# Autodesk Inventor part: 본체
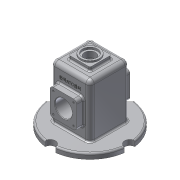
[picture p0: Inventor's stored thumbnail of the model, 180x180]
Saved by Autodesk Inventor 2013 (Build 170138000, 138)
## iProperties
Created: 2018-07
Part Number: 본체
Material: 알루미늄 6061
Document SubType Name: Modeling
Designer: dgall
Density: 1 g/cm^3
Author: dgall
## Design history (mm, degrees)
sketch "스케치1"
  geometry: L1 (-37, -37)-(37, -37); L2 (37, -37)-(37, 37); L3 (37, 37)-(-37, 37); L4 (-37, 37)-(-37, -37); L5 (-37, -37)-(37, 37); L6 (37, -37)-(-37, 37); 1 further point
  constraints: 12 end point, 2 midpoint, 2 parallel, 1 horizontal, 1 perpendicular
  dimensions: "d0" = 74 distance of L3.end L1.start; "d1" = 74 distance of L2.end L3.end
extrude "돌출1" new body sketch "스케치1" distance "d2" = 110; taper "d3" = 0 deg
sketch "스케치2"
  geometry: C1 r 75 at (0, 0); 1 further point
  constraints: 1 centre point, 1 coincident
  dimensions: "d4" = 150 diameter of C1
extrude "돌출2" join sketch "스케치2" distance "d6" = 10; taper "d7" = 0 deg
sketch "스케치3"
  geometry: L1 (-20, -20)-(20, -20); L2 (20, -20)-(20, 20); L3 (20, 20)-(-20, 20); L4 (-20, 20)-(-20, -20); L5 (-20, -20)-(20, 20); L6 (20, -20)-(-20, 20); 1 further point
  constraints: 12 end point, 2 midpoint, 2 parallel, 1 horizontal, 1 perpendicular
  dimensions: "d8" = 40 distance of L2.end L3.end; "d9" = 40 distance of L1.end L2.end
extrude "돌출3" join sketch "스케치3" distance "d10" = 7; taper "d11" = 0 deg
sketch "스케치4"
  geometry: C1 r 75 at (0, 0) reference; C2 r 17.5 at (0, 0); 1 further point
  constraints: 1 centre point, 1 coincident
  dimensions: "d12" = 35 diameter of C2
extrude "돌출4" join sketch "스케치4" distance "d14" = 3; taper "d15" = 0 deg
sketch "스케치5"
  geometry: L1 (-25, 30)-(25, 30); L2 (25, 30)-(25, 80); L3 (25, 80)-(-25, 80); L4 (-25, 80)-(-25, 30); L5 (-25, 30)-(25, 80); L6 (25, 30)-(-25, 80); L7 (-75, 0)-(75, 0) reference; L8 (-37, 10)-(-37, 110) reference; 3 further points
  constraints: 12 end point, 2 midpoint, 2 parallel, 1 horizontal, 1 perpendicular
  dimensions: "d17" = 50 distance of L2.end L3.end; "d19" = 50 distance of L3.end L1.start; "d20" = 55 distance from line of L7 point (0, 55); "d21" = 37 distance from line of L8 point (0, 55)
extrude "돌출5" join sketch "스케치5" stored distance "d22" = 100; taper "d23" = 0 deg
fillet "모깎기2" dims "d24" = 6
fillet "모깎기3" dims "d25" = 3
sketch "스케치6"
  geometry: C1 r 17.5 at (0, 0) reference
hole "구멍1" sketch "스케치6" at (0, 0) diameter "d27" = 21; stored, may be unused: countersink angle "d31" = 90 deg, drill point angle "d33" = 118 deg; dims "d28" = 6, "d29" = 28, "d30" = 4, "d32" = 21
sketch "스케치7"
  geometry: L1 (0, -75)-(0, 75) reference; C1 r 16 at (-55, 0); 2 further points
  constraints: 1 centre point, 1 horizontal alignment, 1 midpoint
  dimensions: "d34" = 32 diameter of C1; "d36" = 55 distance from line of L1 C1.centre
extrude "돌출6" cut sketch "스케치7" stored distance "d37" = 100; taper "d38" = 0 deg
sketch "스케치8"
  geometry: L1 (-32, 0)-(32, 0); L2 (32, 0)-(32, 105); L3 (32, 105)-(-32, 105); L4 (-32, 105)-(-32, 0); L5 (-32, 0)-(32, 105); L6 (32, 0)-(-32, 105); L7 (-29, 110)-(29, 110) reference; 3 further points
  constraints: 12 end point, 3 midpoint, 2 parallel, 1 coincident, 1 horizontal, 1 perpendicular
  dimensions: "d39" = 64 distance of L2.end L3.end; "d41" = 5 distance between parallel lines of L3 L7
extrude "돌출7" cut sketch "스케치8" stored distance "d42" = 64; taper "d43" = 0 deg
sketch "스케치9"
  geometry: L1 (32, 80)-(25, 77.452); L2 (25, 77.452)-(25, 55); L3 (40, 74)-(40, 36) reference; L4 (25, 55)-(32, 55); L5 (32, 55)-(32, 80); L6 (32, 71)-(32, 39) reference; L7 (32, 0)-(-32, 0) reference; L8 (32, 0)-(32, 105) reference; 1 further point
  constraints: 8 end point, 1 collinear, 1 parallel, 1 perpendicular, 1 point on line
  dimensions: "d44" = 55 distance between parallel lines of L7 L4; "d45" = 50 diameter of L1.start L4; "d46" = 7 distance between parallel lines of L6 L2; "d47" = 110 deg angle of L1 L2
revolve "회전1" sketch "스케치9" stored, may be unused: angle "d48" = 90 deg
sketch "스케치10"
  geometry: C1 r 16 at (0, 0) reference; C2 r 16 at (0, 0); 1 further point
  constraints: 1 centre point, 1 coincident
extrude "돌출8" cut sketch "스케치10" stored distance "d49" = 64; taper "d50" = 0 deg
fillet "모깎기5" dims "d51" = 8
fillet "모깎기6" dims "d52" = 8
fillet "모깎기7" dims "d53" = 3
fillet "모깎기8" dims "d54" = 3
fillet "모깎기9" dims "d55" = 3
sketch "스케치11"
  geometry: C1 r 10 at (0, 75); 1 further point
  constraints: 1 centre point, 1 vertical alignment, 1 other
  dimensions: "d56" = 20 diameter of C1
extrude "돌출9" cut sketch "스케치11" stored distance "d59" = 0; taper "d60" = 0 deg
fillet "모깎기10" dims "d64" = 3
fillet "모깎기11" dims "d65" = 3
fillet "모깎기12" dims "d66" = 3
sketch "스케치12"
  geometry: A1 r 6 centre (36, 19) between (36, 25) and (30, 19) reference; A2 r 6 centre (36, -19) between (30, -19) and (36, -25) reference; A3 r 6 centre (74, -19) between (74, -25) and (80, -19) reference; A4 r 6 centre (74, 19) between (80, 19) and (74, 25) reference; 1 further point
hole "구멍2" sketch "스케치12" at (74, -19), (74, 19), (36, 19), (36, -19) diameter "d67" = 3.242; stored, may be unused: countersink angle "d71" = 90 deg, drill point angle "d73" = 118 deg; dims "d68" = 8, "d69" = 28, "d70" = 4, "d72" = 10
sketch "스케치13"
  geometry: A1 r 6 centre (-36, 19) between (-30, 19) and (-36, 25) reference; A2 r 6 centre (-74, 19) between (-74, 25) and (-80, 19) reference; A3 r 6 centre (-74, -19) between (-80, -19) and (-74, -25) reference; A4 r 6 centre (-36, -19) between (-36, -25) and (-30, -19) reference; 1 further point
hole "구멍3" sketch "스케치13" at (-36, 19), (-74, 19), (-74, -19), (-36, -19) diameter "d74" = 3.242; stored, may be unused: countersink angle "d78" = 90 deg, drill point angle "d80" = 118 deg; dims "d75" = 8, "d76" = 28, "d77" = 4, "d79" = 10
sketch "스케치14"
  geometry: L1 (-89, -8)-(0, -8) reference; L2 (18, 11.5)-(18, 46.5) reference; 2 further points
  constraints: 1 other
  dimensions: "d81" = 37 distance from line of L1 point (-12, 29); "d82" = 30 distance from line of L2 point (-12, 29)
feature "엠보싱1" sketch "스케치14" dims "d0" = 74, "d1" = 74, "d41" = 5, "d51" = 8, "d64" = 3, "d83" = 0.5, "d84" = 0
chamfer "모따기1" distance "d85" = 1; stored, may be unused: second distance "d86" = 2, angle "d87" = 45 deg
node "솔리드1"
mirror "대칭1"
pattern_circular "원형 패턴1" dims angle "d62" = 360 deg
